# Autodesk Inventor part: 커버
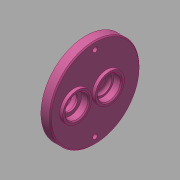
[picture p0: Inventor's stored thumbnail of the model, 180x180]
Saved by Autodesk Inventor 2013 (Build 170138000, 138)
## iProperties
Created: 2016-02
Part Number: 커버
Material: 알루미늄 6061
Document SubType Name: Modeling
Designer: mduedu
Density: 2.71 g/cm^3
Author: mduedu
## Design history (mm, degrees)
sketch "스케치1"
  geometry: C1 r 43 at (0, 0); 1 further point
  constraints: 1 centre point, 1 coincident
  dimensions: "d0" = 86 diameter of C1
extrude "돌출1" new body sketch "스케치1" distance "d1" = 9; taper "d2" = 0 deg
sketch "스케치2"
  geometry: C1 r 14 at (0, 11); 1 further point
  constraints: 1 centre point, 1 vertical alignment
  dimensions: "d3" = 28 diameter of C1; "d6" = 11 distance of C1.centre point (0, 0)
extrude "돌출2" join sketch "스케치2" distance "d7" = 3; taper "d8" = 0 deg
sketch "스케치3"
  geometry: C1 r 14 at (0, -20); 1 further point
  constraints: 1 centre point, 1 vertical alignment
  dimensions: "d9" = 28 diameter of C1; "d10" = 20 distance of C1.centre point (0, 0)
extrude "돌출3" join sketch "스케치3" distance "d11" = 3; taper "d12" = 0 deg
hole "구멍1" diameter "d15" = 22; stored, may be unused: countersink angle "d19" = 90 deg, drill point angle "d21" = 0 deg; dims "d13" = 10, "d14" = 10, "d16" = 6, "d17" = 4, "d18" = 2, "d20" = 7
hole "구멍2" diameter "d24" = 18; stored, may be unused: countersink angle "d28" = 90 deg, drill point angle "d30" = 0 deg; dims "d25" = 6, "d26" = 4, "d27" = 2, "d29" = 3, "d95" = 10, "d96" = 10
fillet "모깎기7" dims "d97" = 3
hole "구멍3" diameter "d33" = 22; stored, may be unused: countersink angle "d37" = 90 deg, drill point angle "d39" = 0 deg; dims "d34" = 6, "d35" = 4, "d36" = 2, "d38" = 7, "d73" = 10, "d74" = 10
sketch "스케치4"
  geometry: C1 r 14 at (0, -20) reference; C2 r 18 at (0, -20); 1 further point
  constraints: 1 centre point, 1 coincident
  dimensions: "d40" = 36 diameter of C2
extrude "돌출4" join sketch "스케치4" distance "d41" = 4; taper "d42" = 0 deg
hole "구멍4" diameter "d45" = 22; stored, may be unused: countersink angle "d49" = 90 deg, drill point angle "d51" = 0 deg; dims "d46" = 6, "d47" = 4, "d48" = 2, "d50" = 7.3, "d98" = 10, "d99" = 10
hole "구멍5" diameter "d54" = 15; stored, may be unused: countersink angle "d58" = 90 deg, drill point angle "d60" = 0 deg; dims "d52" = 10, "d53" = 10, "d55" = 6, "d56" = 4, "d57" = 2, "d59" = 7
chamfer "모따기1" distance "d63" = 1; stored, may be unused: second distance "d64" = 2, angle "d65" = 45 deg
chamfer "모따기3" distance "d100" = 0.7; stored, may be unused: second distance "d101" = 2, angle "d102" = 30 deg
sketch "스케치5" dims "d67" = 72
  geometry: 4 further points
  constraints: 2 horizontal alignment, 1 coincident, 5 other
  dimensions: "d71" = 360 deg dimension on point (0, 0) point (-36, 0) (derived)
sketch "스케치6"
  geometry: 2 further points
hole "구멍6" sketch "스케치6" at (-36, 0), (36, 0) diameter "d76" = 4.5; stored, may be unused: countersink angle "d80" = 90 deg, drill point angle "d82" = 0 deg; dims "d77" = 6, "d78" = 8, "d79" = 4.6, "d81" = 8
chamfer "모따기2" distance "d90" = 1; stored, may be unused: second distance "d91" = 2, angle "d92" = 45 deg
node "솔리드1"
